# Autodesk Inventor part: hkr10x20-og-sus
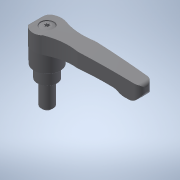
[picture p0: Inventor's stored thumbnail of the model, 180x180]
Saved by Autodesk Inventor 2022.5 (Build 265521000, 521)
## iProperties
Created: 2017-09
Part Number: hkr10x20-og-sus
Material: 一般
Document SubType Name: Modeling
Designer: imaocorp
Density: 1 g/cm^3
Appearance: 既定
Author: imaocorp
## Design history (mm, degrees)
node "hkr10x20-og-sus.x_t1"
node "hkr10x20-og-sus"
node "Base1"
